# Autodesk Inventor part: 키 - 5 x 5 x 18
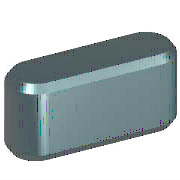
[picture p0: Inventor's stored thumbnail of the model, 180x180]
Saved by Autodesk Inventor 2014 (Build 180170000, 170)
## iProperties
Created: 2012-02
Part Number: 키 - 5 x 5 x 18
Material: 강철, 연강
Description: 키 및 해당 키홈
Document SubType Name: Modeling
Standard: KS B 1311
Designer: mduedu
Standards Organization: KS
Language: ko-KR
Size Designation: 5 x 5 x 18
Categories: <MemberInstance><Categories><Category DisplayName="샤프트 부품" InternalName="7f7aeb1f-a693-4053-b835-cee3144e0d98" Mnemonic="SHFT"><Category DisplayName="키" Interna
Density: 7.86 g/cm^3
Mass: 3.27476 g
Surface Area: 3.57848 cm^2
Volume: 0.416636 cm^3
Appearance: 강철
IsCustomPart: 1
Author: mduedu
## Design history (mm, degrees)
workplane "Work Plane1"
workplane "Work Plane2"
sketch "스케치1"
  geometry: L1 (2.5, 2.5)-(15.5, 2.5); L2 (15.5, -2.5)-(2.5, -2.5); L3 (0, 9.4)-(0, -7.4) reference; L4 (-5, 0)-(30, 0) reference; L5 (18, 0)-(18, 7); A1 r 2.5 centre (2.5, 0) between (2.5, 2.5) and (2.5, -2.5); A2 r 2.5 centre (15.5, 0) between (15.5, -2.5) and (15.5, 2.5)
  constraints: 6 end point, 5 point on circle, 4 tangent, 3 point on line, 2 centre point, 1 horizontal, 1 parallel, 1 perpendicular
  dimensions: "d0" = 2.5 radius of A1 (= 0.5 x PB); "d13" = 2.5 radius of A2 (= 0.5 x PB); "d14" = 18 distance between parallel lines of L5 L3 (= NLG)
extrude "본체1" new body sketch "스케치1" taper "d3" = 0 deg; stored distance "d4" = 10
workplane "Work Plane3"
body "Solid1"
chamfer "모따기1" distance "d8" = 0.4 (= PHH); stored, may be unused: second distance "d9" = 0.4 (= PHH), angle "d15" = 45 deg
other parameters: "d1" = -3 (= -PNT), "d2" = 2 (= PH - PNT), "NLG" = 18 [user parameter; used in 3 equation terms], "PB" = 5 [user parameter; used in 2 equation terms], "PNT" = 3 [user parameter; used in 2 equation terms], "PH" = 5 [user parameter; used in 1 equation term], "PHH" = 0.4 [user parameter; used in 2 equation terms], "d10" = 0, "d16" = 0, "d17" = 0, "d18" = 0, "WDMIN" = 12 [user parameter], "PLB2" = 18 (= NLG) [user parameter], "WDMAX" = 17 [user parameter], "PLB1" = 18 (= NLG) [user parameter], "RR" = 0.16 [user parameter], "PUEB" = 2.3 [user parameter]
